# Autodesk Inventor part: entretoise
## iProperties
Created: 2011-01
Part Number: entretoise
Document SubType Name: Modeling
Designer: eric
Density: 1 g/cm^3
Mass: 1.49854 g
Surface Area: 22.4781 cm^2
Volume: 1.49854 cm^3
Author: eric
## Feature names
1. Base1
